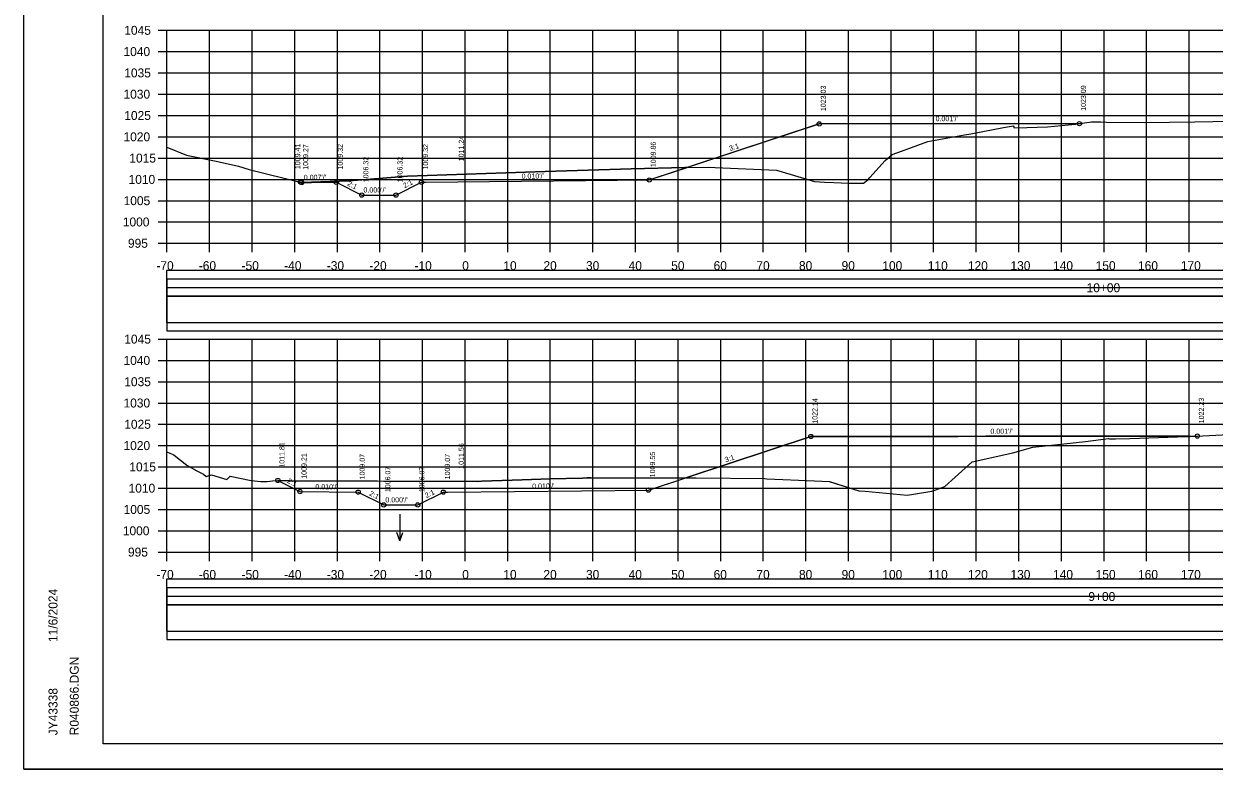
# Model space of a CAD drawing. Extents: x 1370565 to 1374448, y 301010 to 304637.
# Drawn here: x 1373947.9 to 1374227.4, y 302053 to 302228 of the extents above; entities that cross this region are included whole.
import ezdxf

# ---------------------------------------------------------------- set-up
doc = ezdxf.new("R2010")
doc.units = 0
for name, color, linetype in [('Default', 7, 'Continuous'), ('R_Axis', 7, 'Continuous'), ('R_Axis Annot', 7, 'Continuous'), ('R_Border', 7, 'Continuous'), ('R_Contours', 7, 'Continuous'), ('R_Drive', 7, 'Continuous'), ('R_Exist Surface', 7, 'Continuous'), ('R_Fin Surface', 7, 'Continuous'), ('R_Grid', 7, 'Continuous'), ('R_No Plot', 7, 'Continuous'), ('R_Water Annot', 7, 'Continuous'), ('R_Xsect Elev', 7, 'Continuous'), ('R_Xsect Slope', 7, 'Continuous')]:
    doc.layers.add(name, color=color, linetype=linetype)

msp = doc.modelspace()

# ---------------------------------------------------------------- linework, layer by layer
at = {"layer": 'Default'}
for points in [[(1373981.44, 302166.1), (1374421.61, 302166.1), (1374421.61, 302170.09), (1373981.44, 302170.09)], [(1373981.44, 302157.87), (1374421.61, 302157.87), (1374421.61, 302166.02), (1373981.44, 302166.02)], [(1373981.44, 302093.6), (1374421.61, 302093.6), (1374421.61, 302097.59), (1373981.44, 302097.59)], [(1373981.44, 302085.37), (1374421.61, 302085.37), (1374421.61, 302093.52), (1373981.44, 302093.52)]]:
    msp.add_lwpolyline(points, close=True, dxfattribs=at)
at = {"layer": 'R_Axis'}
for p, q in [((1373979.42, 302226.47), (1373981.52, 302226.47)), ((1373981.52, 302176.47), (1373981.52, 302226.47)), ((1373979.42, 302221.47), (1373981.52, 302221.47)), ((1373979.42, 302216.47), (1373981.52, 302216.47)), ((1373979.42, 302211.47), (1373981.52, 302211.47)), ((1373979.42, 302206.47), (1373981.52, 302206.47)), ((1373979.42, 302201.47), (1373981.52, 302201.47)), ((1373979.42, 302196.47), (1373981.52, 302196.47)), ((1373979.42, 302191.47), (1373981.52, 302191.47)), ((1373979.42, 302186.47), (1373981.52, 302186.47)), ((1373979.42, 302181.47), (1373981.52, 302181.47)), ((1373979.42, 302176.47), (1373981.52, 302176.47)), ((1373981.52, 302176.47), (1374421.52, 302176.47)), ((1373981.52, 302174.37), (1373981.52, 302176.47)), ((1373991.52, 302174.37), (1373991.52, 302176.47)), ((1374001.52, 302174.37), (1374001.52, 302176.47)), ((1374011.52, 302174.37), (1374011.52, 302176.47)), ((1374021.52, 302174.37), (1374021.52, 302176.47)), ((1374031.52, 302174.37), (1374031.52, 302176.47)), ((1374041.52, 302174.37), (1374041.52, 302176.47)), ((1374051.52, 302174.37), (1374051.52, 302176.47)), ((1374061.52, 302174.37), (1374061.52, 302176.47)), ((1374071.52, 302174.37), (1374071.52, 302176.47)), ((1374081.52, 302174.37), (1374081.52, 302176.47)), ((1374091.52, 302174.37), (1374091.52, 302176.47)), ((1374101.52, 302174.37), (1374101.52, 302176.47)), ((1374111.52, 302174.37), (1374111.52, 302176.47)), ((1374121.52, 302174.37), (1374121.52, 302176.47)), ((1374131.52, 302174.37), (1374131.52, 302176.47)), ((1374141.52, 302174.37), (1374141.52, 302176.47)), ((1374151.52, 302174.37), (1374151.52, 302176.47)), ((1374161.52, 302174.37), (1374161.52, 302176.47)), ((1374171.52, 302174.37), (1374171.52, 302176.47)), ((1374181.52, 302174.37), (1374181.52, 302176.47)), ((1374191.52, 302174.37), (1374191.52, 302176.47)), ((1374201.52, 302174.37), (1374201.52, 302176.47)), ((1374211.52, 302174.37), (1374211.52, 302176.47)), ((1374221.52, 302174.37), (1374221.52, 302176.47)), ((1373979.42, 302153.97), (1373981.52, 302153.97)), ((1373981.52, 302103.97), (1373981.52, 302153.97)), ((1373979.42, 302148.97), (1373981.52, 302148.97)), ((1373979.42, 302143.97), (1373981.52, 302143.97)), ((1373979.42, 302138.97), (1373981.52, 302138.97)), ((1373979.42, 302133.97), (1373981.52, 302133.97)), ((1373979.42, 302128.97), (1373981.52, 302128.97)), ((1373979.42, 302123.97), (1373981.52, 302123.97)), ((1373979.42, 302118.97), (1373981.52, 302118.97)), ((1373979.42, 302113.97), (1373981.52, 302113.97)), ((1373979.42, 302108.97), (1373981.52, 302108.97)), ((1373979.42, 302103.97), (1373981.52, 302103.97)), ((1373981.52, 302103.97), (1374421.52, 302103.97)), ((1373981.52, 302101.87), (1373981.52, 302103.97)), ((1373991.52, 302101.87), (1373991.52, 302103.97)), ((1374001.52, 302101.87), (1374001.52, 302103.97)), ((1374011.52, 302101.87), (1374011.52, 302103.97)), ((1374021.52, 302101.87), (1374021.52, 302103.97)), ((1374031.52, 302101.87), (1374031.52, 302103.97)), ((1374041.52, 302101.87), (1374041.52, 302103.97)), ((1374051.52, 302101.87), (1374051.52, 302103.97)), ((1374061.52, 302101.87), (1374061.52, 302103.97)), ((1374071.52, 302101.87), (1374071.52, 302103.97)), ((1374081.52, 302101.87), (1374081.52, 302103.97)), ((1374091.52, 302101.87), (1374091.52, 302103.97)), ((1374101.52, 302101.87), (1374101.52, 302103.97)), ((1374111.52, 302101.87), (1374111.52, 302103.97)), ((1374121.52, 302101.87), (1374121.52, 302103.97)), ((1374131.52, 302101.87), (1374131.52, 302103.97)), ((1374141.52, 302101.87), (1374141.52, 302103.97)), ((1374151.52, 302101.87), (1374151.52, 302103.97)), ((1374161.52, 302101.87), (1374161.52, 302103.97)), ((1374171.52, 302101.87), (1374171.52, 302103.97)), ((1374181.52, 302101.87), (1374181.52, 302103.97)), ((1374191.52, 302101.87), (1374191.52, 302103.97)), ((1374201.52, 302101.87), (1374201.52, 302103.97)), ((1374211.52, 302101.87), (1374211.52, 302103.97)), ((1374221.52, 302101.87), (1374221.52, 302103.97))]:
    msp.add_line(p, q, dxfattribs=at)
at = {"layer": 'R_Border'}
for p, q in [((1373966.52, 302058.97), (1373966.52, 302367.16)), ((1373966.52, 302058.97), (1373966.52, 302058.97)), ((1374440.79, 302058.97), (1373966.52, 302058.97))]:
    msp.add_line(p, q, dxfattribs=at)
at = {"layer": 'R_Contours'}
for p, q in [((1374134.66, 302204.5), (1374103.65, 302194.27)), ((1374195.29, 302204.56), (1374134.66, 302204.5)), ((1374015.42, 302190.82), (1374013.13, 302190.74)), ((1374013.13, 302190.74), (1374015.42, 302190.75)), ((1374015.42, 302190.75), (1374021.27, 302190.79)), ((1374103.08, 302121.33), (1374081.03, 302121.37))]:
    msp.add_line(p, q, dxfattribs=at)
for points in [[(1374103.65, 302194.27), (1374108.69, 302194.36), (1374110.2, 302194.3), (1374124.63, 302193.66), (1374128.03, 302192.62), (1374133.51, 302191), (1374135.91, 302190.84), (1374138.1, 302190.73), (1374141.49, 302190.6), (1374145.01, 302190.59), (1374146.07, 302191.36), (1374146.56, 302191.91), (1374150.1, 302195.93), (1374151.81, 302197.33), (1374153.99, 302198.13), (1374160.19, 302200.38), (1374168.79, 302201.91), (1374170.21, 302202.18), (1374177.91, 302203.67), (1374180.28, 302204.05), (1374180.4, 302203.61), (1374183.37, 302203.67), (1374188.28, 302203.82), (1374194.8, 302204.43), (1374195.3, 302204.5)], [(1374195.3, 302204.5), (1374195.29, 302204.56)], [(1374103.65, 302194.27), (1374103.14, 302194.26), (1374090.47, 302193.97), (1374070.32, 302193.33), (1374037.96, 302192.26), (1374029.33, 302191.56), (1374024.23, 302191.14), (1374015.42, 302190.82)], [(1374021.27, 302190.79), (1374027.27, 302187.79), (1374035.27, 302187.79), (1374041.27, 302190.79), (1374042.27, 302190.8), (1374094.74, 302191.33), (1374103.65, 302194.27)], [(1374015.42, 302190.82), (1374015.42, 302190.75)], [(1374015.42, 302190.75), (1374015.42, 302190.82)], [(1374221.31, 302131.2), (1374195.94, 302131.17), (1374187.45, 302131.16), (1374186.07, 302131.16), (1374177.89, 302131.15), (1374173.76, 302131.15), (1374167.31, 302131.14), (1374157.51, 302131.13), (1374132.7, 302131.11), (1374103.11, 302121.34)], [(1374103.11, 302121.33), (1374104.15, 302121.42), (1374105.73, 302121.4), (1374121.82, 302121.22), (1374122.34, 302121.2), (1374133.56, 302120.73), (1374136.99, 302120.58), (1374143.96, 302118.37), (1374145.46, 302118.24), (1374155.33, 302117.37), (1374156.79, 302117.6), (1374161.07, 302118.24), (1374162.05, 302118.62), (1374164.14, 302119.35), (1374166.54, 302121.59), (1374170.54, 302125.12), (1374180.12, 302127.3), (1374184.79, 302128.57), (1374197.18, 302129.97), (1374202.55, 302130.62), (1374202.84, 302130.55), (1374204.25, 302130.57), (1374207.59, 302130.63), (1374218.78, 302131.04), (1374221.31, 302131.1)], [(1374221.31, 302131.1), (1374221.31, 302131.2)], [(1374081.03, 302121.37), (1374080.65, 302121.38), (1374080.09, 302121.39), (1374079.11, 302121.36), (1374071.46, 302121.19), (1374064.91, 302120.93), (1374055.46, 302120.63), (1374054.34, 302120.52), (1374051.52, 302120.53), (1374010.44, 302120.71), (1374007.57, 302120.77)], [(1374007.57, 302120.77), (1374012.75, 302118.18), (1374026.41, 302118.04), (1374032.41, 302115.04), (1374040.41, 302115.04), (1374046.41, 302118.04), (1374047.41, 302118.05), (1374094.57, 302118.53), (1374103.08, 302121.33)], [(1374103.11, 302121.34), (1374103.11, 302121.33)]]:
    msp.add_lwpolyline(points, dxfattribs=at)
at = {"layer": 'R_Drive'}
for points in [[(1373981.52, 302164.06), (1374421.73, 302164.06), (1374421.73, 302168.05), (1373981.52, 302168.05)], [(1373981.52, 302155.91), (1374421.73, 302155.91), (1374421.73, 302164.06), (1373981.52, 302164.06)], [(1373981.52, 302091.58), (1374421.73, 302091.58), (1374421.73, 302095.57), (1373981.52, 302095.57)], [(1373981.52, 302083.44), (1374421.73, 302083.44), (1374421.73, 302091.58), (1373981.52, 302091.58)]]:
    msp.add_lwpolyline(points, close=True, dxfattribs=at)
at = {"layer": 'R_Exist Surface'}
for points in [[(1373981.52, 302199.07), (1373986.09, 302197.12), (1373993.1, 302195.76), (1373998.35, 302194.61), (1374000.81, 302193.78), (1374013.07, 302190.74), (1374015.42, 302190.82), (1374024.23, 302191.14), (1374029.33, 302191.56), (1374037.96, 302192.26), (1374070.32, 302193.33), (1374090.47, 302193.97), (1374103.14, 302194.26), (1374108.69, 302194.36), (1374110.2, 302194.3), (1374124.63, 302193.66), (1374128.03, 302192.62), (1374133.51, 302191), (1374135.91, 302190.84), (1374138.1, 302190.73), (1374141.49, 302190.6), (1374145.01, 302190.59), (1374146.07, 302191.36), (1374146.56, 302191.91), (1374150.1, 302195.93), (1374151.81, 302197.33), (1374153.99, 302198.13), (1374160.19, 302200.38), (1374168.79, 302201.91), (1374170.21, 302202.18), (1374177.91, 302203.67), (1374180.28, 302204.05), (1374180.3, 302203.99), (1374180.4, 302203.61), (1374183.37, 302203.67), (1374188.28, 302203.82), (1374194.8, 302204.43), (1374198.54, 302204.96), (1374200.79, 302204.98), (1374202.13, 302204.94), (1374210.94, 302204.86), (1374222.83, 302205), (1374227.05, 302205.09), (1374230.56, 302205.17)], [(1373981.52, 302127.47), (1373982.2, 302127.18), (1373982.95, 302126.85), (1373983.25, 302126.74), (1373986.19, 302124.38), (1373988.52, 302123.01), (1373990.13, 302122.29), (1373990.71, 302121.71), (1373991.97, 302122.08), (1373995.61, 302121.04), (1373996.38, 302121.76), (1374001.26, 302120.77), (1374003.57, 302120.57), (1374005.01, 302120.56), (1374005.01, 302120.56), (1374006.96, 302120.78), (1374007.01, 302120.79), (1374010.44, 302120.71), (1374054.34, 302120.52), (1374055.46, 302120.63), (1374064.91, 302120.93), (1374071.46, 302121.19), (1374079.11, 302121.36), (1374080.09, 302121.39), (1374080.65, 302121.38), (1374081.03, 302121.37), (1374103.11, 302121.33), (1374104.15, 302121.42), (1374105.73, 302121.4), (1374121.82, 302121.22), (1374122.34, 302121.2), (1374133.56, 302120.73), (1374136.99, 302120.58), (1374137.08, 302120.55), (1374143.96, 302118.37), (1374145.46, 302118.24), (1374155.33, 302117.37), (1374156.79, 302117.6), (1374161.07, 302118.24), (1374162.05, 302118.62), (1374164.14, 302119.35), (1374166.54, 302121.59), (1374170.54, 302125.12), (1374180.12, 302127.3), (1374184.79, 302128.57), (1374197.18, 302129.97), (1374202.55, 302130.62), (1374202.84, 302130.55), (1374204.25, 302130.57), (1374207.59, 302130.63), (1374218.78, 302131.04), (1374221.69, 302131.11), (1374238.38, 302131.97)]]:
    msp.add_lwpolyline(points, dxfattribs=at)
at = {"layer": 'R_Fin Surface'}
for points in [[(1374013.13, 302190.74), (1374013.13, 302190.74), (1374021.27, 302190.79), (1374027.27, 302187.79), (1374035.27, 302187.79), (1374041.27, 302190.79), (1374042.27, 302190.8), (1374094.74, 302191.33), (1374134.66, 302204.5), (1374195.29, 302204.56), (1374195.73, 302204.56)], [(1374007.55, 302120.78), (1374012.75, 302118.18), (1374026.41, 302118.04), (1374032.41, 302115.04), (1374040.41, 302115.04), (1374046.41, 302118.04), (1374047.41, 302118.05), (1374094.57, 302118.53), (1374132.7, 302131.11), (1374157.51, 302131.13), (1374167.31, 302131.14), (1374173.76, 302131.15), (1374177.89, 302131.15), (1374186.07, 302131.16), (1374187.45, 302131.16), (1374195.94, 302131.17), (1374221.31, 302131.2), (1374223.43, 302131.2)]]:
    msp.add_lwpolyline(points, dxfattribs=at)
at = {"layer": 'R_Grid'}
for p, q in [((1373981.52, 302226.47), (1374421.52, 302226.47)), ((1373981.52, 302176.47), (1373981.52, 302226.47)), ((1373991.52, 302176.47), (1373991.52, 302226.47)), ((1374001.52, 302176.47), (1374001.52, 302226.47)), ((1374011.52, 302176.47), (1374011.52, 302226.47)), ((1374021.52, 302176.47), (1374021.52, 302226.47)), ((1374031.52, 302176.47), (1374031.52, 302226.47)), ((1374041.52, 302176.47), (1374041.52, 302226.47)), ((1374051.52, 302176.47), (1374051.52, 302226.47)), ((1374061.52, 302176.47), (1374061.52, 302226.47)), ((1374071.52, 302176.47), (1374071.52, 302226.47)), ((1374081.52, 302176.47), (1374081.52, 302226.47)), ((1374091.52, 302176.47), (1374091.52, 302226.47)), ((1374101.52, 302176.47), (1374101.52, 302226.47)), ((1374111.52, 302176.47), (1374111.52, 302226.47)), ((1374121.52, 302176.47), (1374121.52, 302226.47)), ((1374131.52, 302176.47), (1374131.52, 302226.47)), ((1374141.52, 302176.47), (1374141.52, 302226.47)), ((1374151.52, 302176.47), (1374151.52, 302226.47)), ((1374161.52, 302176.47), (1374161.52, 302226.47)), ((1374171.52, 302176.47), (1374171.52, 302226.47)), ((1374181.52, 302176.47), (1374181.52, 302226.47)), ((1374191.52, 302176.47), (1374191.52, 302226.47)), ((1374201.52, 302176.47), (1374201.52, 302226.47)), ((1374211.52, 302176.47), (1374211.52, 302226.47)), ((1374221.52, 302176.47), (1374221.52, 302226.47)), ((1373981.52, 302221.47), (1374421.52, 302221.47)), ((1373981.52, 302216.47), (1374421.52, 302216.47)), ((1373981.52, 302211.47), (1374421.52, 302211.47)), ((1373981.52, 302206.47), (1374421.52, 302206.47)), ((1373981.52, 302201.47), (1374421.52, 302201.47)), ((1373981.52, 302196.47), (1374421.52, 302196.47)), ((1373981.52, 302191.47), (1374421.52, 302191.47)), ((1373981.52, 302186.47), (1374421.52, 302186.47)), ((1373981.52, 302181.47), (1374421.52, 302181.47)), ((1373981.52, 302176.47), (1374421.52, 302176.47)), ((1373981.52, 302153.97), (1374421.52, 302153.97)), ((1373981.52, 302103.97), (1373981.52, 302153.97)), ((1373991.52, 302103.97), (1373991.52, 302153.97)), ((1374001.52, 302103.97), (1374001.52, 302153.97)), ((1374011.52, 302103.97), (1374011.52, 302153.97)), ((1374021.52, 302103.97), (1374021.52, 302153.97)), ((1374031.52, 302103.97), (1374031.52, 302153.97)), ((1374041.52, 302103.97), (1374041.52, 302153.97)), ((1374051.52, 302103.97), (1374051.52, 302153.97)), ((1374061.52, 302103.97), (1374061.52, 302153.97)), ((1374071.52, 302103.97), (1374071.52, 302153.97)), ((1374081.52, 302103.97), (1374081.52, 302153.97)), ((1374091.52, 302103.97), (1374091.52, 302153.97)), ((1374101.52, 302103.97), (1374101.52, 302153.97)), ((1374111.52, 302103.97), (1374111.52, 302153.97)), ((1374121.52, 302103.97), (1374121.52, 302153.97)), ((1374131.52, 302103.97), (1374131.52, 302153.97)), ((1374141.52, 302103.97), (1374141.52, 302153.97)), ((1374151.52, 302103.97), (1374151.52, 302153.97)), ((1374161.52, 302103.97), (1374161.52, 302153.97)), ((1374171.52, 302103.97), (1374171.52, 302153.97)), ((1374181.52, 302103.97), (1374181.52, 302153.97)), ((1374191.52, 302103.97), (1374191.52, 302153.97)), ((1374201.52, 302103.97), (1374201.52, 302153.97)), ((1374211.52, 302103.97), (1374211.52, 302153.97)), ((1374221.52, 302103.97), (1374221.52, 302153.97)), ((1373981.52, 302148.97), (1374421.52, 302148.97)), ((1373981.52, 302143.97), (1374421.52, 302143.97)), ((1373981.52, 302138.97), (1374421.52, 302138.97)), ((1373981.52, 302133.97), (1374421.52, 302133.97)), ((1373981.52, 302128.97), (1374421.52, 302128.97)), ((1373981.52, 302123.97), (1374421.52, 302123.97)), ((1373981.52, 302118.97), (1374421.52, 302118.97)), ((1373981.52, 302113.97), (1374421.52, 302113.97)), ((1373981.52, 302108.97), (1374421.52, 302108.97)), ((1373981.52, 302103.97), (1374421.52, 302103.97))]:
    msp.add_line(p, q, dxfattribs=at)
at = {"layer": 'R_No Plot'}
msp.add_line((1373947.92, 302053), (1374447.92, 302053), dxfattribs=at)
for points in [[(1373947.91, 302373), (1374447.92, 302373), (1374447.92, 302053), (1373947.91, 302053)], [(1374317.4, 302367.16), (1374346.83, 302367.16), (1374346.83, 302352.34), (1374371, 302352.34), (1374405.8, 302352.34), (1374405.98, 302310.11), (1374440.79, 302310.11), (1374440.79, 302058.97), (1373966.52, 302058.97), (1373966.52, 302367.16)]]:
    msp.add_lwpolyline(points, close=True, dxfattribs=at)
for centre in [(1374134.66, 302204.5), (1374195.73, 302204.56), (1374012.86, 302190.88), (1374013.13, 302190.74), (1374021.27, 302190.79), (1374041.27, 302190.79), (1374094.74, 302191.33), (1374027.27, 302187.79), (1374035.27, 302187.79), (1374132.7, 302131.11), (1374223.43, 302131.2), (1374007.55, 302120.78), (1374012.75, 302118.18), (1374026.41, 302118.04), (1374046.41, 302118.04), (1374094.57, 302118.53), (1374032.41, 302115.04), (1374040.41, 302115.04)]:
    msp.add_circle(centre, 0.5, dxfattribs=at)
at = {"layer": 'R_Water Annot'}
for p, q in [((1374036.21, 302112.9), (1374036.21, 302106.61)), ((1374036.21, 302106.61), (1374035.51, 302108.54)), ((1374036.21, 302106.61), (1374036.91, 302108.54))]:
    msp.add_line(p, q, dxfattribs=at)
at = {"layer": 'R_Xsect Elev'}
for p, q in [((1374051.52, 302192.71), (1374051.52, 302202.71)), ((1374051.52, 302120.53), (1374051.52, 302130.53))]:
    msp.add_line(p, q, dxfattribs=at)

# ---------------------------------------------------------------- texts
at = {"layer": 'R_Axis Annot'}
for s, p in [('1045', (1373971.5, 302225.42)), ('1040', (1373971.32, 302220.42)), ('1035', (1373971.5, 302215.42)), ('1030', (1373971.32, 302210.42)), ('1025', (1373971.5, 302205.42)), ('1020', (1373971.32, 302200.42)), ('1015', (1373972.69, 302195.42)), ('1010', (1373972.51, 302190.42)), ('1005', (1373971.34, 302185.42)), ('1000', (1373971.16, 302180.42)), ('995', (1373972.36, 302175.42)), ('-70', (1373979.04, 302170.17)), ('-60', (1373988.99, 302170.17)), ('-50', (1373999.04, 302170.17)), ('-40', (1374009.04, 302170.17)), ('-30', (1374019.04, 302170.17)), ('-20', (1374029.04, 302170.17)), ('-10', (1374039.63, 302170.17)), ('0', (1374050.84, 302170.17)), ('10', (1374060.49, 302170.17)), ('20', (1374069.9, 302170.17)), ('30', (1374079.9, 302170.17)), ('40', (1374089.9, 302170.17)), ('50', (1374099.9, 302170.17)), ('60', (1374109.85, 302170.17)), ('70', (1374119.9, 302170.17)), ('80', (1374129.9, 302170.17)), ('90', (1374139.9, 302170.17)), ('100', (1374149.47, 302170.17)), ('110', (1374160.14, 302170.17)), ('120', (1374169.55, 302170.17)), ('130', (1374179.55, 302170.17)), ('140', (1374189.55, 302170.17)), ('150', (1374199.55, 302170.17)), ('160', (1374209.5, 302170.17)), ('170', (1374219.55, 302170.17)), ('10+00', (1374197.42, 302164.98)), ('1045', (1373971.5, 302152.92)), ('1040', (1373971.32, 302147.92)), ('1035', (1373971.5, 302142.92)), ('1030', (1373971.32, 302137.92)), ('1025', (1373971.5, 302132.92)), ('1020', (1373971.32, 302127.92)), ('1015', (1373972.69, 302122.92)), ('1010', (1373972.51, 302117.92)), ('1005', (1373971.34, 302112.92)), ('1000', (1373971.16, 302107.92)), ('995', (1373972.36, 302102.92)), ('-70', (1373979.04, 302097.67)), ('-60', (1373988.99, 302097.67)), ('-50', (1373999.04, 302097.67)), ('-40', (1374009.04, 302097.67)), ('-30', (1374019.04, 302097.67)), ('-20', (1374029.04, 302097.67)), ('-10', (1374039.63, 302097.67)), ('0', (1374050.84, 302097.67)), ('10', (1374060.49, 302097.67)), ('20', (1374069.9, 302097.67)), ('30', (1374079.9, 302097.67)), ('40', (1374089.9, 302097.67)), ('50', (1374099.9, 302097.67)), ('60', (1374109.85, 302097.67)), ('70', (1374119.9, 302097.67)), ('80', (1374129.9, 302097.67)), ('90', (1374139.9, 302097.67)), ('100', (1374149.47, 302097.67)), ('110', (1374160.14, 302097.67)), ('120', (1374169.55, 302097.67)), ('130', (1374179.55, 302097.67)), ('140', (1374189.55, 302097.67)), ('150', (1374199.55, 302097.67)), ('160', (1374209.5, 302097.67)), ('170', (1374219.55, 302097.67)), ('9+00', (1374197.84, 302092.48))]:
    msp.add_text(s, height=2.1, dxfattribs=at).set_placement(p)
at = {"layer": 'R_Border'}
for s, p in [('11/6/2024', (1373955.82, 302082.86)), ('R040866.DGN', (1373960.81, 302060.96)), ('JY43338', (1373955.82, 302060.96))]:
    msp.add_text(s, height=2.1, rotation=90, dxfattribs=at).set_placement(p)
at = {"layer": 'R_Xsect Elev'}
for s, p in [('1023.03', (1374136.21, 302207.5)), ('1023.09', (1374197.28, 302207.56)), ('1011.24', (1374051.22, 302195.71)), ('1009.41', (1374012.82, 302193.88)), ('1009.27', (1374014.68, 302193.74)), ('1009.32', (1374022.82, 302193.79)), ('1009.32', (1374042.82, 302193.79)), ('1009.86', (1374096.29, 302194.33)), ('1006.32', (1374028.82, 302190.79)), ('1006.32', (1374036.82, 302190.79)), ('1022.14', (1374134.25, 302134.11)), ('1022.23', (1374224.98, 302134.2)), ('1011.81', (1374009.1, 302123.78)), ('1011.56', (1374051.22, 302123.53)), ('1009.21', (1374014.3, 302121.18)), ('1009.07', (1374027.96, 302121.04)), ('1009.07', (1374047.96, 302121.04)), ('1009.55', (1374096.12, 302121.53)), ('1006.07', (1374033.96, 302118.04)), ('1006.07', (1374041.96, 302118.04))]:
    msp.add_text(s, height=1.2, rotation=90, dxfattribs=at).set_placement(p)
at = {"layer": 'R_Xsect Slope'}
for s, rotation, p in [("0.001'/'", 0.0573, (1374161.97, 302205.13)), ('3:1', 18.2629, (1374113.75, 302198.13)), ("0.007'/'", 0.3877, (1374013.64, 302191.34)), ("0.010'/'", 0.5729, (1374064.78, 302191.63)), ('2:1', 333.4349, (1374023.75, 302190.11)), ("0.000'/'", 360, (1374027.66, 302188.39)), ('2:1', 26.5651, (1374037.31, 302189.37)), ("0.001'/'", 0.0573, (1374174.85, 302131.75)), ('3:1', 18.2629, (1374112.69, 302125.03)), ('2:1', 333.4349, (1374009.63, 302120.3)), ("0.010'/'", 359.4271, (1374016.37, 302118.74)), ("0.010'/'", 0.5729, (1374067.27, 302118.85)), ('2:1', 333.4349, (1374028.89, 302117.36)), ("0.000'/'", 360, (1374032.8, 302115.64)), ('2:1', 26.5651, (1374042.44, 302116.62))]:
    msp.add_text(s, height=1.2, rotation=rotation, dxfattribs=at).set_placement(p)

doc.saveas('drawing.dxf')
